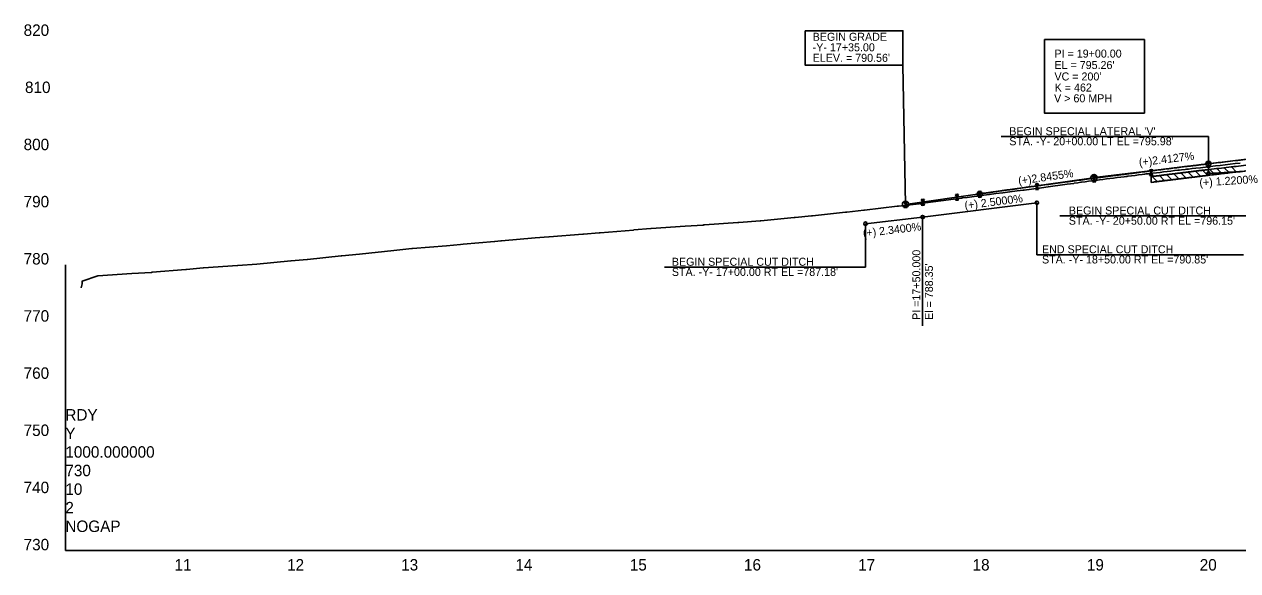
# Model space of a CAD drawing. Extents: x 579185 to 595036, y -53221 to -44640.
# Drawn here: x 579290 to 580352, y -47238 to -46760 of the extents above; entities that cross this region are included whole.
import ezdxf

# ---------------------------------------------------------------- set-up
doc = ezdxf.new("R2010")
doc.units = 0
for name, color, linetype in [('Exist Profile Cell', 7, 'Continuous'), ('Exist Vertical Profile Ground Line', 7, 'Continuous'), ('Exist Vertical Profile Horizontal Axis Label Major', 7, 'Continuous'), ('Exist Vertical Profile Vertical Axis Label', 7, 'Continuous'), ('Old_Level_2', 7, 'Continuous'), ('Prop Grid Mask', 7, 'Continuous'), ('Prop Vertical Profile Curve Label', 7, 'Continuous'), ('Prop Vertical Profile Ditch Grade Left', 7, 'Continuous'), ('Prop Vertical Profile Ditch Grade Left Label', 7, 'Continuous'), ('Prop Vertical Profile Ditch Grade Right', 7, 'Continuous'), ('Prop Vertical Profile Ditch Grade Right Label', 7, 'Continuous'), ('Prop Vertical Profile Grade', 7, 'Continuous'), ('Prop Vertical Profile Grade Label', 7, 'Continuous'), ('Prop VPI Ditch Grade Right Label', 7, 'Continuous'), ('Prop VPI Label', 7, 'Continuous'), ('Scratch_Level_1', 7, 'Continuous')]:
    doc.layers.add(name, color=color, linetype=linetype)

msp = doc.modelspace()

# ---------------------------------------------------------------- linework, layer by layer
at = {"layer": 'Exist Profile Cell'}
for q in [(579326.2, -46970.5), (584953.7, -47220.5), (579326.2, -47220.5)]:
    msp.add_line((579326.2, -47220.5), q, dxfattribs=at)
at = {"layer": 'Exist Vertical Profile Ground Line'}
for points in [[(580249.5, -46893.9), (580252.6, -46893.5), (580254.1, -46893.3), (580254.8, -46893.2), (580255.8, -46893.1), (580258.9, -46892.7), (580262, -46892.3), (580265.1, -46891.9), (580268.3, -46891.5), (580270.3, -46891.3), (580271.4, -46891.1), (580273.4, -46890.9), (580274.5, -46890.7), (580274.9, -46890.7), (580277.6, -46890.4), (580280.8, -46890), (580283.9, -46889.7), (580287, -46889.3), (580290.1, -46888.9), (580293.3, -46888.6), (580296.4, -46888.2), (580299.5, -46887.9), (580300.8, -46887.7), (580302.6, -46887.5), (580305.8, -46887.1), (580307.1, -46887), (580308.9, -46886.8), (580312, -46886.4), (580315.1, -46886.1), (580319.4, -46885.6), (580321.2, -46885.4), (580323.7, -46885.1), (580325.5, -46884.9), (580328, -46884.6), (580332.3, -46884.1), (580336.6, -46883.6), (580341, -46883), (580345.3, -46882.5), (580349.6, -46882), (580353.9, -46881.6)], [(579339.9, -46990.8), (579340.9, -46987.2), (579340.9, -46985), (579354.6, -46980.3), (579384.4, -46978.3), (579401.7, -46977.2), (579402.1, -46977.1), (579431.7, -46974.6), (579432.1, -46974.6), (579446.7, -46973.3), (579447.1, -46973.3), (579476.7, -46971.1), (579477, -46971.1), (579493.8, -46969.9), (579523.4, -46967.1), (579523.8, -46967.1), (579537.6, -46965.8), (579538.1, -46965.8), (579567.6, -46962.8), (579568, -46962.8), (579583.6, -46961.2), (579613.5, -46958.1), (579629.4, -46956.4), (579629.8, -46956.4), (579659.7, -46953.9), (579671.8, -46952.8), (579674.3, -46952.6), (579701.5, -46950.2), (579702, -46950.2), (579707.1, -46949.7), (579707.7, -46949.7), (579737.1, -46947.1), (579749.1, -46946.1), (579749.5, -46946), (579779, -46943.7), (579779.4, -46943.7), (579793.3, -46942.6), (579794, -46942.5), (579823.3, -46940.2), (579823.6, -46940.1), (579838.4, -46938.9), (579838.8, -46938.9), (579868.3, -46936.9), (579884.2, -46935.8), (579884.9, -46935.7), (579885.3, -46935.7), (579914.5, -46933.6), (579915.4, -46933.6), (579934.2, -46932.2), (579934.7, -46932.2), (579963.7, -46929.3), (579964.8, -46929.2), (579979.1, -46927.8), (579979.9, -46927.8), (580008.7, -46924.5), (580009.8, -46924.4), (580024.7, -46922.8), (580025.2, -46922.7), (580054, -46919.3), (580055.2, -46919.2), (580073.1, -46917.1), (580074.2, -46916.9), (580103.1, -46913.2), (580110.3, -46912.2), (580111.2, -46912.1), (580115.1, -46911.6), (580127.6, -46909.9), (580134.1, -46909.1), (580134.6, -46909), (580140.1, -46908.3), (580146.4, -46907.5), (580152.6, -46906.7), (580158.9, -46905.9), (580164.1, -46905.3), (580165.1, -46905.2), (580171.4, -46904.4), (580177.6, -46903.6), (580178, -46903.5), (580178.4, -46903.5), (580183.9, -46902.7), (580190.1, -46901.8), (580196.4, -46901), (580202.6, -46900.1), (580208.4, -46899.3), (580208.9, -46899.2), (580212, -46898.8), (580214.5, -46898.4), (580215.1, -46898.4), (580218.3, -46897.9), (580221.4, -46897.5), (580224.5, -46897.1), (580225, -46897), (580225.3, -46897), (580227.6, -46896.7), (580230.8, -46896.3), (580233.9, -46895.9), (580237, -46895.5), (580240.1, -46895.1), (580243.3, -46894.7), (580246.4, -46894.3), (580249.5, -46893.9)]]:
    msp.add_lwpolyline(points, dxfattribs=at)
at = {"layer": 'Old_Level_2'}
for p, q in [((580326.2, -46882.7), (580324.8, -46880.2)), ((580324.8, -46880.2), (580327.7, -46880.2)), ((580326.2, -46882.7), (580327.7, -46880.2)), ((580276.2, -46889.9), (580274.8, -46887.4)), ((580274.8, -46887.4), (580277.7, -46887.4)), ((580274.8, -46892.4), (580276.2, -46889.9)), ((580275.3, -46888.3), (580277.2, -46888.3)), ((580275.8, -46889.1), (580276.7, -46889.1)), ((580275.8, -46890.8), (580276.7, -46890.8)), ((580276.2, -46889.9), (580277.7, -46887.4)), ((580277.7, -46892.4), (580276.2, -46889.9)), ((580324.8, -46885.2), (580326.2, -46882.7)), ((580324.8, -46885.2), (580327.7, -46885.2)), ((580325.3, -46881.1), (580327.2, -46881.1)), ((580325.3, -46884.4), (580327.2, -46884.4)), ((580325.8, -46881.9), (580326.7, -46881.9)), ((580325.8, -46883.6), (580326.7, -46883.6)), ((580327.7, -46885.2), (580326.2, -46882.7)), ((580176.2, -46902.2), (580174.8, -46899.7)), ((580174.8, -46899.7), (580177.7, -46899.7)), ((580175.3, -46900.5), (580177.2, -46900.5)), ((580175.8, -46901.3), (580176.7, -46901.3)), ((580176.2, -46902.2), (580177.7, -46899.7)), ((580226.2, -46895.6), (580224.8, -46893.1)), ((580224.8, -46893.1), (580227.7, -46893.1)), ((580224.8, -46898.1), (580226.2, -46895.6)), ((580224.8, -46898.1), (580227.7, -46898.1)), ((580225.3, -46894), (580227.2, -46894)), ((580225.3, -46897.3), (580227.2, -46897.3)), ((580225.8, -46894.8), (580226.7, -46894.8)), ((580225.8, -46896.5), (580226.7, -46896.5)), ((580226.2, -46895.6), (580227.7, -46893.1)), ((580227.7, -46898.1), (580226.2, -46895.6)), ((580274.8, -46892.4), (580277.7, -46892.4)), ((580275.3, -46891.6), (580277.2, -46891.6)), ((580106.2, -46911.6), (580104.8, -46909.1)), ((580104.8, -46909.1), (580107.7, -46909.1)), ((580104.8, -46914.1), (580106.2, -46911.6)), ((580105.3, -46909.9), (580107.2, -46909.9)), ((580105.8, -46910.8), (580106.7, -46910.8)), ((580106.2, -46911.6), (580107.7, -46909.1)), ((580107.7, -46914.1), (580106.2, -46911.6)), ((580126.2, -46908.8), (580124.8, -46906.3)), ((580124.8, -46906.3), (580127.7, -46906.3)), ((580124.8, -46911.3), (580126.2, -46908.8)), ((580124.8, -46911.3), (580127.7, -46911.3)), ((580125.3, -46907.2), (580127.2, -46907.2)), ((580125.3, -46910.5), (580127.2, -46910.5)), ((580125.8, -46908), (580126.7, -46908)), ((580125.8, -46909.7), (580126.7, -46909.7)), ((580126.2, -46908.8), (580127.7, -46906.3)), ((580127.7, -46911.3), (580126.2, -46908.8)), ((580174.8, -46904.7), (580176.2, -46902.2)), ((580174.8, -46904.7), (580177.7, -46904.7)), ((580175.3, -46903.8), (580177.2, -46903.8)), ((580175.8, -46903), (580176.7, -46903)), ((580177.7, -46904.7), (580176.2, -46902.2)), ((580061.2, -46917.8), (580059.8, -46915.3)), ((580059.8, -46915.3), (580062.7, -46915.3)), ((580059.8, -46920.3), (580061.2, -46917.8)), ((580059.8, -46920.3), (580062.7, -46920.3)), ((580060.3, -46916.1), (580062.2, -46916.1)), ((580060.3, -46919.4), (580062.2, -46919.4)), ((580060.8, -46916.9), (580061.7, -46916.9)), ((580060.8, -46918.6), (580061.7, -46918.6)), ((580061.2, -46917.8), (580062.7, -46915.3)), ((580062.7, -46920.3), (580061.2, -46917.8)), ((580076.2, -46915.8), (580074.8, -46913.3)), ((580074.8, -46913.3), (580077.7, -46913.3)), ((580074.8, -46918.3), (580076.2, -46915.8)), ((580074.8, -46918.3), (580077.7, -46918.3)), ((580075.3, -46914.2), (580077.2, -46914.2)), ((580075.3, -46917.5), (580077.2, -46917.5)), ((580075.8, -46915), (580076.7, -46915)), ((580075.8, -46916.7), (580076.7, -46916.7)), ((580076.2, -46915.8), (580077.7, -46913.3)), ((580077.7, -46918.3), (580076.2, -46915.8)), ((580104.8, -46914.1), (580107.7, -46914.1)), ((580105.3, -46913.3), (580107.2, -46913.3)), ((580105.8, -46912.4), (580106.7, -46912.4))]:
    msp.add_line(p, q, dxfattribs=at)
at = {"layer": 'Prop Grid Mask'}
for points in [[(579973.5, -46765.8), (580058.9, -46765.8), (580058.9, -46796), (579973.5, -46796)], [(580182.8, -46773.6), (580270.2, -46773.6), (580270.2, -46837.8), (580182.8, -46837.8)]]:
    msp.add_lwpolyline(points, close=True, dxfattribs=at)
at = {"layer": 'Prop Vertical Profile Curve Label'}
msp.add_line((580061.2, -46917.8), (580058.9, -46796), dxfattribs=at)
for centre in [(580326.2, -46882.2), (580326.2, -46882.2), (580126.2, -46908.5)]:
    msp.add_circle(centre, 2.25, dxfattribs=at)
at = {"layer": 'Prop Vertical Profile Ditch Grade Left'}
msp.add_lwpolyline([(580326.2, -46890.6), (580376.2, -46887.6), (580426.2, -46884.3), (580476.2, -46878.3)], dxfattribs=at)
at = {"layer": 'Prop Vertical Profile Ditch Grade Left Label'}
for p in [(580144.9, -46858.3), (580326.2, -46890.6)]:
    msp.add_line(p, (580326.2, -46858.3), dxfattribs=at)
msp.add_circle((580326.2, -46890.6), 1.5, dxfattribs=at)
at = {"layer": 'Prop Vertical Profile Ditch Grade Right'}
msp.add_lwpolyline([(580026.2, -46934.6), (580076.2, -46928.8), (580176.2, -46916.3)], dxfattribs=at)
at = {"layer": 'Prop Vertical Profile Ditch Grade Right Label'}
for p, q in [((580176.2, -46916.3), (580176.2, -46961.8)), ((580076.2, -46928.8), (580076.2, -47023.9)), ((580196.1, -46927.7), (580376.2, -46927.7)), ((580026.2, -46934.6), (580026.2, -46972.6)), ((580176.2, -46961.8), (580356.8, -46961.8)), ((579850.4, -46972.6), (580026.2, -46972.6))]:
    msp.add_line(p, q, dxfattribs=at)
at = {"layer": 'Prop Vertical Profile Grade'}
msp.add_line((580061.2, -46917.7), (580126.2, -46908.5), dxfattribs=at)
for points in [[(580326.2, -46882.2), (580334.8, -46881.2), (580343.4, -46880.2), (580352, -46879.2), (580360.6, -46878.3), (580369.2, -46877.4), (580377.8, -46876.5), (580386.4, -46875.6), (580395, -46874.7), (580403.6, -46873.9), (580412.2, -46873.1), (580420.8, -46872.4), (580429.4, -46871.6), (580438, -46870.9), (580446.6, -46870.3), (580455.2, -46869.6), (580463.8, -46869), (580472.4, -46868.4), (580481, -46867.8), (580489.6, -46867.2), (580498.2, -46866.7), (580506.8, -46866.2), (580515.4, -46865.7), (580524, -46865.3), (580532.6, -46864.9), (580541.2, -46864.5), (580549.8, -46864.1), (580558.4, -46863.8), (580567, -46863.4), (580575.6, -46863.1), (580584.2, -46862.9), (580592.8, -46862.6), (580601.4, -46862.4), (580610, -46862.2), (580618.6, -46862.1), (580627.2, -46862), (580635.8, -46861.8), (580644.4, -46861.8), (580653, -46861.7), (580661.6, -46861.7), (580670.2, -46861.7), (580678.8, -46861.7), (580687.4, -46861.8), (580696, -46861.8), (580704.6, -46861.9), (580713.2, -46862.1), (580721.8, -46862.2), (580730.4, -46862.4), (580739, -46862.6), (580747.6, -46862.8), (580756.2, -46863.1)], [(580126.2, -46908.5), (580130.2, -46907.9), (580134.2, -46907.4), (580138.2, -46906.8), (580142.2, -46906.2), (580146.2, -46905.7), (580150.2, -46905.1), (580154.2, -46904.6), (580158.2, -46904), (580162.2, -46903.4), (580166.2, -46902.9), (580170.2, -46902.3), (580174.2, -46901.8), (580178.2, -46901.2), (580182.2, -46900.7), (580186.2, -46900.2), (580190.2, -46899.6), (580194.2, -46899.1), (580198.2, -46898.5), (580202.2, -46898), (580206.2, -46897.5), (580210.2, -46896.9), (580214.2, -46896.4), (580218.2, -46895.9), (580222.2, -46895.3), (580226.2, -46894.8), (580230.2, -46894.3), (580234.2, -46893.8), (580238.2, -46893.2), (580242.2, -46892.7), (580246.2, -46892.2), (580250.2, -46891.7), (580254.2, -46891.2), (580258.2, -46890.7), (580262.2, -46890.2), (580266.2, -46889.6), (580270.2, -46889.1), (580274.2, -46888.6), (580278.2, -46888.1), (580282.2, -46887.6), (580286.2, -46887.1), (580290.2, -46886.6), (580294.2, -46886.1), (580298.2, -46885.6), (580302.2, -46885.1), (580306.2, -46884.6), (580310.2, -46884.2), (580314.2, -46883.7), (580318.2, -46883.2), (580322.2, -46882.7), (580326.2, -46882.2)]]:
    msp.add_spline(points, degree=3, dxfattribs=at)
at = {"layer": 'Prop VPI Ditch Grade Right Label'}
for centre in [(580176.2, -46916.3), (580026.2, -46934.6), (580076.2, -46928.8)]:
    msp.add_circle(centre, 1.5, dxfattribs=at)
at = {"layer": 'Prop VPI Label'}
for p, q in [((580326.2, -46882.2), (580538.5, -46856.6)), ((580326.2, -46882.2), (580229, -46893.9)), ((580126.2, -46908.5), (580223.5, -46894.7))]:
    msp.add_line(p, q, dxfattribs=at)
for centre in [(580226.2, -46894.3), (580061.2, -46917.7)]:
    msp.add_circle(centre, 2.75, dxfattribs=at)
at = {"layer": 'Scratch_Level_1'}
for p, q in [((580295.9, -46891), (580300.4, -46895.4)), ((580302.2, -46890.2), (580306.7, -46894.7)), ((580308.5, -46889.4), (580313, -46893.9)), ((580314.8, -46888.6), (580319.3, -46893.1)), ((580321.1, -46887.9), (580325.6, -46892.4)), ((580327.4, -46887.1), (580331.9, -46891.6)), ((580333.7, -46886.4), (580338.2, -46890.9)), ((580340.1, -46885.6), (580344.6, -46890.1)), ((580346.4, -46884.9), (580350.9, -46889.4)), ((580276.2, -46898.5), (580276.2, -46893.4)), ((580277.1, -46893.3), (580281.5, -46897.8)), ((580283.3, -46892.5), (580287.8, -46897)), ((580289.6, -46891.7), (580294.1, -46896.2))]:
    msp.add_line(p, q, dxfattribs=at)
msp.add_spline([(580326.8, -46887.2), (580335.4, -46886.2), (580344, -46885.2), (580352.6, -46884.2), (580361.2, -46883.2), (580369.8, -46882.3), (580378.3, -46881.4), (580386.9, -46880.6), (580395.5, -46879.7), (580404.1, -46878.9), (580412.7, -46878.1), (580421.3, -46877.4), (580429.9, -46876.6), (580438.4, -46875.9), (580447, -46875.2), (580455.6, -46874.6), (580464.2, -46874), (580472.8, -46873.3), (580481.4, -46872.8), (580489.9, -46872.2), (580498.5, -46871.7), (580507.1, -46871.2), (580515.7, -46870.7), (580524.3, -46870.3), (580532.9, -46869.9), (580541.5, -46869.5), (580550, -46869.1), (580558.6, -46868.7), (580567.2, -46868.4), (580575.8, -46868.1), (580584.4, -46867.9), (580593, -46867.6), (580601.6, -46867.4), (580610.1, -46867.2), (580618.7, -46867.1), (580626.2, -46867)], degree=3, dxfattribs=at)
for points in [[(580327.4, -46892.1), (580330.3, -46891.8), (580333.1, -46891.5), (580336, -46891.1), (580338.9, -46890.8), (580341.7, -46890.5), (580344.6, -46890.1), (580347.4, -46889.8), (580350.3, -46889.5), (580353.1, -46889.2), (580356, -46888.8), (580358.9, -46888.5), (580361.7, -46888.2), (580364.6, -46887.9), (580367.4, -46887.6), (580370.3, -46887.3), (580373.1, -46887), (580376, -46886.7), (580378.9, -46886.4), (580381.7, -46886.1), (580384.6, -46885.8), (580387.4, -46885.5), (580390.3, -46885.3), (580393.1, -46885), (580396, -46884.7), (580398.9, -46884.4), (580401.7, -46884.2), (580404.6, -46883.9), (580407.4, -46883.6), (580410.3, -46883.4), (580413.1, -46883.1), (580416, -46882.8), (580418.8, -46882.6), (580421.7, -46882.3), (580424.6, -46882.1), (580427.4, -46881.9), (580430.3, -46881.6), (580433.1, -46881.4), (580436, -46881.1), (580438.8, -46880.9), (580441.7, -46880.7), (580444.6, -46880.4), (580447.4, -46880.2), (580450.3, -46880), (580453.1, -46879.8), (580456, -46879.6), (580458.8, -46879.4), (580461.7, -46879.1), (580464.6, -46878.9), (580467.4, -46878.7), (580470.3, -46878.5), (580473.1, -46878.3), (580476, -46878.1), (580478.8, -46877.9), (580481.7, -46877.8), (580484.5, -46877.6), (580487.4, -46877.4), (580490.3, -46877.2), (580493.1, -46877), (580496, -46876.9), (580498.8, -46876.7), (580501.7, -46876.5), (580504.5, -46876.3), (580507.4, -46876.2), (580510.3, -46876), (580513.1, -46875.9), (580516, -46875.7), (580518.8, -46875.6), (580521.7, -46875.4), (580524.5, -46875.3), (580527.4, -46875.1), (580530.3, -46875), (580533.1, -46874.8), (580536, -46874.7), (580538.8, -46874.6), (580541.7, -46874.5), (580544.5, -46874.3), (580547.4, -46874.2), (580550.3, -46874.1), (580553.1, -46874), (580556, -46873.9), (580558.8, -46873.7), (580561.7, -46873.6), (580564.5, -46873.5), (580567.4, -46873.4), (580570.2, -46873.3), (580573.1, -46873.2), (580576, -46873.1), (580578.8, -46873), (580581.7, -46873), (580584.5, -46872.9), (580587.4, -46872.8), (580590.2, -46872.7), (580593.1, -46872.6), (580596, -46872.6), (580598.8, -46872.5), (580601.7, -46872.4), (580604.5, -46872.4), (580607.4, -46872.3), (580610.2, -46872.2), (580613.1, -46872.2), (580616, -46872.1), (580618.8, -46872.1), (580621.3, -46872), (580623.7, -46872), (580626.2, -46872)], [(580276.2, -46893.4), (580277.1, -46893.3), (580278, -46893.2), (580278.9, -46893.1), (580280.2, -46892.9), (580281.5, -46892.8), (580282.9, -46892.6), (580284.2, -46892.4), (580285.5, -46892.3), (580286.9, -46892.1), (580288.2, -46891.9), (580289.5, -46891.8), (580290.9, -46891.6), (580292.2, -46891.4), (580293.5, -46891.3), (580294.9, -46891.1), (580296.2, -46890.9), (580297.5, -46890.8), (580298.9, -46890.6), (580300.2, -46890.4), (580301.5, -46890.3), (580302.8, -46890.1), (580304.2, -46889.9), (580305.5, -46889.8), (580306.8, -46889.6), (580308.2, -46889.4), (580309.5, -46889.3), (580310.8, -46889.1), (580312.2, -46889), (580313.5, -46888.8), (580314.8, -46888.6), (580316.2, -46888.5), (580317.5, -46888.3), (580318.8, -46888.1), (580320.2, -46888), (580321.5, -46887.8), (580322.8, -46887.7), (580324.2, -46887.5), (580325.5, -46887.3), (580326.8, -46887.2)], [(580276.2, -46898.5), (580277.3, -46898.3), (580278.4, -46898.2), (580279.5, -46898), (580280.8, -46897.9), (580282.1, -46897.7), (580283.5, -46897.5), (580284.8, -46897.4), (580286.1, -46897.2), (580287.5, -46897), (580288.8, -46896.9), (580290.1, -46896.7), (580291.5, -46896.5), (580292.8, -46896.4), (580294.1, -46896.2), (580295.5, -46896.1), (580296.8, -46895.9), (580298.1, -46895.7), (580299.5, -46895.6), (580300.8, -46895.4), (580302.1, -46895.2), (580303.5, -46895.1), (580304.8, -46894.9), (580306.1, -46894.7), (580307.5, -46894.6), (580308.8, -46894.4), (580310.1, -46894.2), (580311.5, -46894.1), (580312.8, -46893.9), (580314.1, -46893.8), (580315.4, -46893.6), (580316.8, -46893.4), (580318.1, -46893.3), (580319.4, -46893.1), (580320.8, -46892.9), (580322.1, -46892.8), (580323.4, -46892.6), (580324.8, -46892.5), (580326.1, -46892.3), (580327.4, -46892.1)]]:
    msp.add_open_spline(points, degree=3, dxfattribs=at)

# ---------------------------------------------------------------- texts
at = {"layer": 'Exist Profile Cell'}
for s, p in [('RDY', (579326.2, -47106.8)), ('Y', (579326.2, -47123)), ('1000.000000', (579326.2, -47139.3)), ('730', (579326.2, -47155.5)), ('10', (579326.2, -47171.8)), ('2', (579326.2, -47188)), ('NOGAP', (579326.2, -47204.3))]:
    msp.add_text(s, height=10, dxfattribs=at).set_placement(p)
at = {"layer": 'Exist Vertical Profile Horizontal Axis Label Major'}
for s, p in [('11', (579421.7, -47238)), ('12', (579520.2, -47238)), ('13', (579620, -47238)), ('14', (579719.9, -47238)), ('15', (579820, -47238)), ('16', (579919.9, -47238)), ('17', (580019.8, -47238)), ('18', (580119.9, -47238)), ('19', (580219.9, -47238)), ('20', (580318.6, -47238))]:
    msp.add_text(s, height=10, dxfattribs=at).set_placement(p)
at = {"layer": 'Exist Vertical Profile Vertical Axis Label'}
for s, p in [('820', (579289.7, -46770.3)), ('810', (579290.9, -46820.3)), ('800', (579289.7, -46870.3)), ('790', (579289.7, -46920.3)), ('780', (579289.7, -46970.3)), ('770', (579289.7, -47020.3)), ('760', (579289.7, -47070.3)), ('750', (579289.7, -47120.3)), ('740', (579289.7, -47170.3)), ('730', (579289.7, -47220.3))]:
    msp.add_text(s, height=10, dxfattribs=at).set_placement(p)
at = {"layer": 'Old_Level_2'}
for p in [(580326, -46880.1), (580276, -46887.3), (580325.8, -46886.2), (580176, -46899.5), (580225.8, -46899.1), (580226, -46893), (580275.8, -46893.4), (580076, -46913.2), (580106, -46908.9), (580125.8, -46912.3), (580126, -46906.2), (580175.8, -46905.7), (580060.8, -46921.3), (580061, -46915.1), (580075.8, -46919.3), (580105.8, -46915.1)]:
    msp.add_text('6"', height=0.8, dxfattribs=at).set_placement(p)
at = {"layer": 'Prop Vertical Profile Curve Label'}
for s, p in [("VC = 200'", (580191.5, -46809.3)), ('K = 462', (580191.7, -46819)), ('V > 60 MPH', (580191.2, -46828.4))]:
    msp.add_text(s, height=7, dxfattribs=at).set_placement(p)
at = {"layer": 'Prop Vertical Profile Ditch Grade Left'}
msp.add_text('(+) 1.2200%', height=7, rotation=3.4907, dxfattribs=at).set_placement((580318.5, -46902.1))
at = {"layer": 'Prop Vertical Profile Ditch Grade Left Label'}
for s, p in [("STA. -Y- 20+00.00 LT EL =795.98'", (580152, -46866)), ("BEGIN SPECIAL LATERAL 'V'", (580152, -46857.2))]:
    msp.add_text(s, height=7, dxfattribs=at).set_placement(p)
at = {"layer": 'Prop Vertical Profile Ditch Grade Right Label'}
for s, rotation, p in [('(+) 2.5000%', 7.125, (580113.3, -46922.1)), ('(+) 2.3400%', 6.6733, (580024.3, -46946.4))]:
    msp.add_text(s, height=7, rotation=rotation, dxfattribs=at).set_placement(p)
for s, p in [('BEGIN SPECIAL CUT DITCH', (580204.1, -46926.6)), ("STA. -Y- 20+50.00 RT EL =796.15'", (580204.1, -46935.5)), ('END SPECIAL CUT DITCH', (580180.6, -46960.5)), ('BEGIN SPECIAL CUT DITCH', (579856.8, -46971.4)), ("STA. -Y- 18+50.00 RT EL =790.85'", (580180.6, -46969.4)), ("STA. -Y- 17+00.00 RT EL =787.18'", (579856.8, -46980.3))]:
    msp.add_text(s, height=7, dxfattribs=at).set_placement(p)
at = {"layer": 'Prop Vertical Profile Grade Label'}
for s, rotation, p in [('(+)2.4127%', 6.8786, (580265.8, -46884.4)), ('(+)2.8455%', 8.0973, (580160.3, -46900.6))]:
    msp.add_text(s, height=7, rotation=rotation, dxfattribs=at).set_placement(p)
at = {"layer": 'Prop VPI Ditch Grade Right Label'}
for s, p in [('PI =17+50.000', (580074.2, -47018.8)), ("El = 788.35'", (580085.2, -47018.8))]:
    msp.add_text(s, height=7, rotation=90, dxfattribs=at).set_placement(p)
at = {"layer": 'Prop VPI Label'}
for s, p in [('BEGIN GRADE', (579980, -46774.6)), ('-Y- 17+35.00', (579980, -46783.8)), ('PI = 19+00.00', (580191.5, -46789.3)), ("ELEV. = 790.56'", (579980, -46793)), ("EL = 795.26'", (580191.5, -46799.3))]:
    msp.add_text(s, height=7, dxfattribs=at).set_placement(p)

doc.saveas('drawing.dxf')
